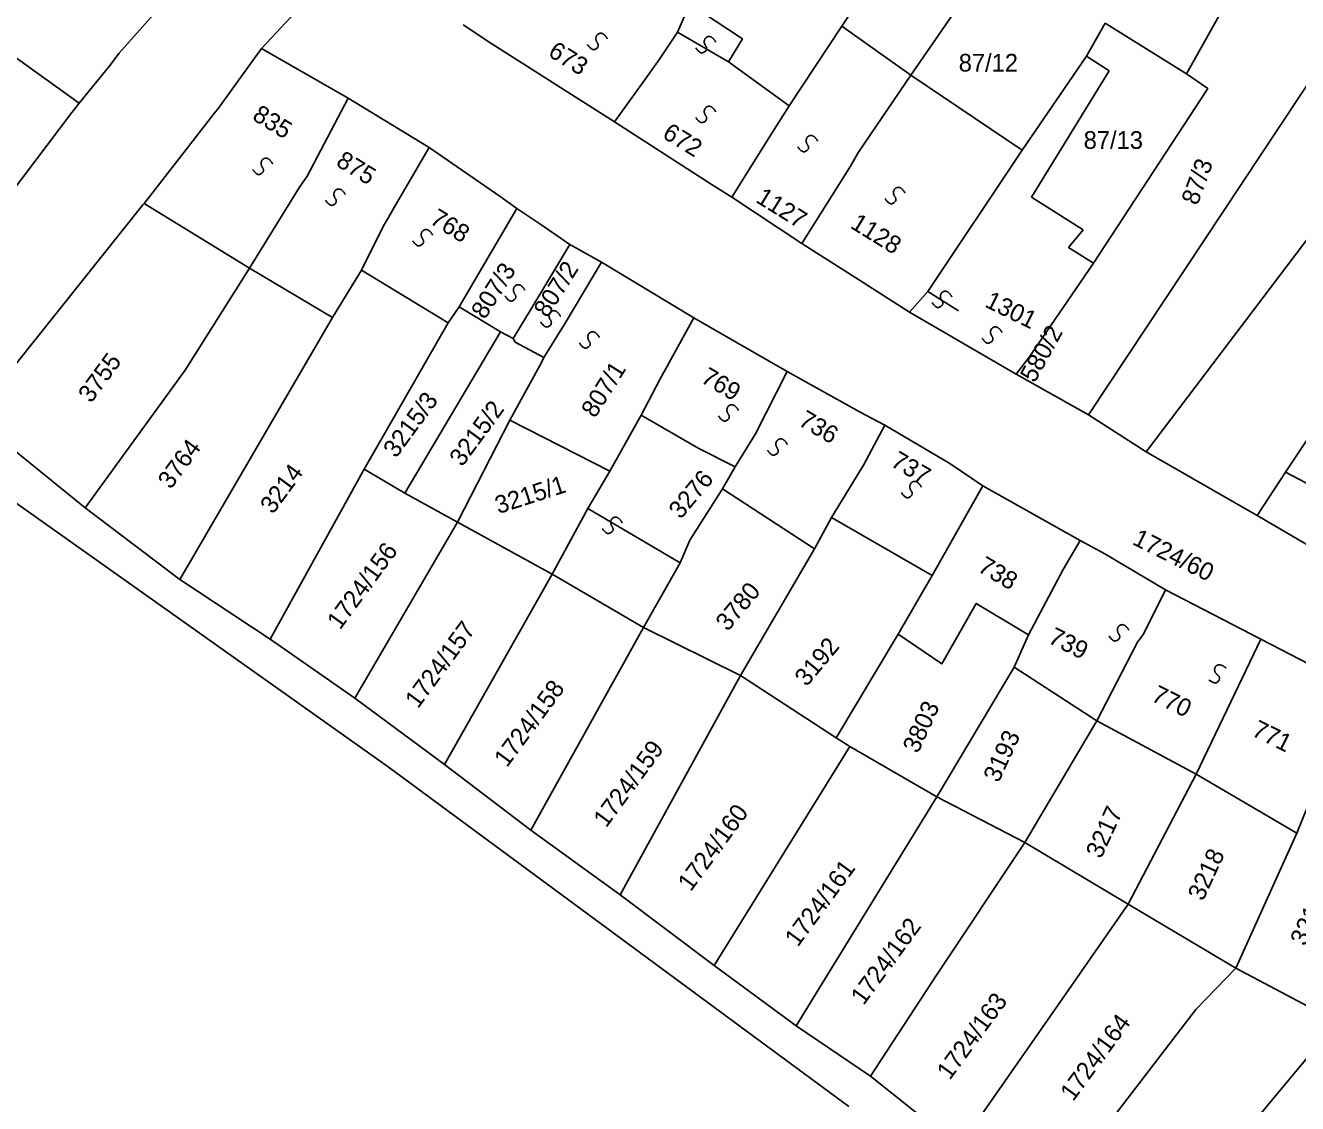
# Model space of a CAD drawing. Extents: x -581999 to -572728, y -1219553 to -1212032.
# Drawn here: x -578351.7 to -578208.2, y -1215913.8 to -1215792.1 of the extents above; entities that cross this region are included whole.
import ezdxf

# ---------------------------------------------------------------- set-up
doc = ezdxf.new("R2010")
doc.units = 0
for name, color, linetype in [('Vrstva 1', 7, 'Continuous'), ('Vrstva 2', 7, 'Continuous'), ('Vrstva 4', 7, 'Continuous'), ('Vrstva 6', 7, 'Continuous')]:
    doc.layers.add(name, color=color, linetype=linetype)

msp = doc.modelspace()

# ---------------------------------------------------------------- linework, layer by layer
at = {"layer": 'Vrstva 1'}
for p, q in [((-578325.082, -1215794.665), (-578314.583, -1215783.383)), ((-578229.44, -1215797.188), (-578231.995, -1215795.54)), ((-578238.201, -1215811.469), (-578229.44, -1215797.188)), ((-578232.36, -1215815.13), (-578238.201, -1215811.469)), ((-578234.003, -1215817.144), (-578232.36, -1215815.13)), ((-578294.134, -1215823.186), (-578290.3, -1215816.778)), ((-578258.024, -1215820.546), (-578264.092, -1215816.665)), ((-578231.196, -1215818.915), (-578234.003, -1215817.144)), ((-578251.957, -1215824.427), (-578258.024, -1215820.546)), ((-578296.689, -1215827.397), (-578294.134, -1215823.186))]:
    msp.add_line(p, q, dxfattribs=at)
for points in [[(-578248.644, -1215775.593), (-578259.602, -1215792.151)], [(-578251.82, -1215797.67), (-578238.821, -1215778.882)], [(-578201.443, -1215790.286), (-578210.075, -1215785.563), (-578215.455, -1215788.156), (-578220.697, -1215797.517)], [(-578278.147, -1215792.82), (-578276.753, -1215789.682)], [(-578276.753, -1215789.682), (-578270.823, -1215793.585), (-578272.401, -1215796.19)], [(-578341.196, -1215795.228), (-578336.766, -1215790.241)], [(-578231.766, -1215836.027), (-578201.443, -1215790.286)], [(-578299.101, -1215794.162), (-578302.325, -1215791.994)], [(-578280.191, -1215795.89), (-578278.147, -1215792.82)], [(-578265.545, -1215801.146), (-578259.602, -1215792.151)], [(-578259.602, -1215792.151), (-578251.82, -1215797.67)], [(-578229.866, -1215791.81), (-578231.995, -1215795.54), (-578239.244, -1215806.132)], [(-578220.697, -1215797.517), (-578229.866, -1215791.81)], [(-578356.273, -1215793.251), (-578345.656, -1215800.846)], [(-578285.27, -1215802.943), (-578299.101, -1215794.162)], [(-578345.656, -1215800.846), (-578342.189, -1215796.566), (-578341.196, -1215795.228)], [(-578325.082, -1215794.665), (-578330.06, -1215801.573), (-578330.304, -1215801.849)], [(-578315.328, -1215800.266), (-578325.082, -1215794.665)], [(-578281.583, -1215797.844), (-578280.191, -1215795.89)], [(-578272.401, -1215796.19), (-578265.545, -1215801.146)], [(-578285.27, -1215802.943), (-578281.583, -1215797.844)], [(-578257.697, -1215806.38), (-578251.82, -1215797.67)], [(-578251.82, -1215797.67), (-578239.244, -1215806.132)], [(-578231.196, -1215818.915), (-578218.29, -1215799.2), (-578220.697, -1215797.517)], [(-578345.656, -1215800.846), (-578346.32, -1215801.667)], [(-578319.926, -1215809.096), (-578315.328, -1215800.266)], [(-578306.151, -1215805.863), (-578315.328, -1215800.266)], [(-578267.402, -1215804.124), (-578265.545, -1215801.146)], [(-578367.768, -1215830.009), (-578346.507, -1215801.898), (-578346.32, -1215801.667)], [(-578330.304, -1215801.849), (-578338.202, -1215811.998), (-578338.344, -1215812.157)], [(-578274.243, -1215810.054), (-578285.27, -1215802.943)], [(-578272.018, -1215811.456), (-578267.402, -1215804.124)], [(-578310.771, -1215813.742), (-578310.219, -1215812.793), (-578306.151, -1215805.863)], [(-578306.151, -1215805.863), (-578298.174, -1215811.369)], [(-578258.621, -1215807.945), (-578257.697, -1215806.38)], [(-578239.244, -1215806.132), (-578249.884, -1215822.088), (-578251.957, -1215824.427)], [(-578264.092, -1215816.665), (-578258.621, -1215807.945)], [(-578320.812, -1215810.318), (-578319.926, -1215809.096)], [(-578272.018, -1215811.456), (-578274.243, -1215810.054)], [(-578326.437, -1215819.457), (-578320.812, -1215810.318)], [(-578298.174, -1215811.369), (-578296.263, -1215812.718)], [(-578264.092, -1215816.665), (-578272.018, -1215811.456)], [(-578338.344, -1215812.157), (-578338.485, -1215812.315), (-578357.631, -1215836.292), (-578345.01, -1215846.507)], [(-578326.437, -1215819.457), (-578338.344, -1215812.157)], [(-578302.784, -1215823.848), (-578296.263, -1215812.718)], [(-578296.263, -1215812.718), (-578293.683, -1215814.455)], [(-578225.23, -1215840.186), (-578204.682, -1215813.018), (-578194.518, -1215819.709)], [(-578311.323, -1215814.691), (-578310.771, -1215813.742)], [(-578293.683, -1215814.455), (-578290.3, -1215816.778), (-578286.706, -1215818.796)], [(-578313.813, -1215819.682), (-578311.323, -1215814.691)], [(-578286.706, -1215818.796), (-578290.824, -1215825.685)], [(-578286.706, -1215818.796), (-578276.291, -1215825.067)], [(-578345.01, -1215846.507), (-578333.714, -1215830.97), (-578326.437, -1215819.457)], [(-578317.068, -1215825.054), (-578326.437, -1215819.457)], [(-578317.068, -1215825.054), (-578313.813, -1215819.682)], [(-578304.02, -1215825.65), (-578313.813, -1215819.682)], [(-578238.437, -1215829.515), (-578231.196, -1215818.915)], [(-578304.02, -1215825.65), (-578302.784, -1215823.848)], [(-578302.784, -1215823.848), (-578298.101, -1215826.646)], [(-578239.915, -1215831.443), (-578251.957, -1215824.427)], [(-578334.303, -1215854.603), (-578317.068, -1215825.054)], [(-578313.5, -1215842.151), (-578304.02, -1215825.65)], [(-578290.824, -1215825.685), (-578293.227, -1215829.541)], [(-578280.123, -1215832.05), (-578276.291, -1215825.067)], [(-578276.291, -1215825.067), (-578273.872, -1215826.482), (-578265.782, -1215831.145)], [(-578308.912, -1215844.852), (-578298.101, -1215826.646)], [(-578298.101, -1215826.646), (-578296.689, -1215827.397), (-578296.476, -1215827.804), (-578293.227, -1215829.541)], [(-578293.227, -1215829.541), (-578293.505, -1215830.098), (-578297.048, -1215836.622)], [(-578239.915, -1215831.443), (-578238.437, -1215829.515)], [(-578265.782, -1215831.145), (-578269.325, -1215838.148)], [(-578257.523, -1215835.708), (-578265.782, -1215831.145)], [(-578231.766, -1215836.027), (-578239.915, -1215831.443)], [(-578201.475, -1215830.426), (-578209.516, -1215842.511)], [(-578282.226, -1215836.06), (-578280.123, -1215832.05)], [(-578285.769, -1215842.392), (-578282.226, -1215836.06)], [(-578282.226, -1215836.06), (-578275.731, -1215839.822), (-578271.623, -1215841.889)], [(-578254.748, -1215837.192), (-578257.523, -1215835.708)], [(-578225.23, -1215840.186), (-578231.766, -1215836.027)], [(-578297.048, -1215836.622), (-578302.986, -1215848.134)], [(-578297.048, -1215836.622), (-578285.769, -1215842.392)], [(-578257.141, -1215841.701), (-578254.748, -1215837.192)], [(-578247.393, -1215841.533), (-578254.748, -1215837.192)], [(-578269.325, -1215838.148), (-578271.623, -1215841.889)], [(-578402.132, -1215909.667), (-578391.501, -1215876.535), (-578369.675, -1215849.108), (-578360.87, -1215840.289), (-578310.778, -1215875.757), (-578269.515, -1215906.185), (-578258.822, -1215914.078)], [(-578212.731, -1215847.387), (-578225.23, -1215840.186)], [(-578260.777, -1215847.615), (-578257.141, -1215841.701)], [(-578243.669, -1215844.039), (-578247.393, -1215841.533)], [(-578324.128, -1215861.338), (-578313.5, -1215842.151)], [(-578313.5, -1215842.151), (-578308.912, -1215844.852)], [(-578288.258, -1215846.612), (-578285.769, -1215842.392)], [(-578271.623, -1215841.889), (-578273.06, -1215844.382)], [(-578209.516, -1215842.511), (-578212.731, -1215847.387)], [(-578273.06, -1215844.382), (-578276.738, -1215850.181), (-578277.847, -1215852.727), (-578281.963, -1215860.016)], [(-578273.06, -1215844.382), (-578262.692, -1215851.164)], [(-578249.411, -1215854.172), (-578243.669, -1215844.039)], [(-578232.687, -1215850.21), (-578243.669, -1215844.039)], [(-578308.912, -1215844.852), (-578302.986, -1215848.134)], [(-578345.01, -1215846.507), (-578334.303, -1215854.603)], [(-578292.28, -1215853.998), (-578288.258, -1215846.612)], [(-578202.918, -1215853.089), (-578212.731, -1215847.387)], [(-578302.986, -1215848.134), (-578314.57, -1215867.99)], [(-578302.986, -1215848.134), (-578292.28, -1215853.998)], [(-578260.777, -1215847.615), (-578262.692, -1215851.164)], [(-578249.411, -1215854.172), (-578260.777, -1215847.615)], [(-578232.687, -1215850.21), (-578234.608, -1215853.48)], [(-578229.92, -1215851.706), (-578232.687, -1215850.21)], [(-578262.692, -1215851.164), (-578271.021, -1215865.452)], [(-578223.075, -1215855.774), (-578229.92, -1215851.706)], [(-578324.128, -1215861.338), (-578334.303, -1215854.603)], [(-578304.439, -1215875.483), (-578292.28, -1215853.998)], [(-578292.28, -1215853.998), (-578281.963, -1215860.016)], [(-578253.241, -1215860.788), (-578249.411, -1215854.172)], [(-578234.608, -1215853.48), (-578238.528, -1215860.855)], [(-578223.075, -1215855.774), (-578225.565, -1215860.76)], [(-578212.307, -1215861.346), (-578223.075, -1215855.774)], [(-578238.528, -1215860.855), (-578244.416, -1215857.303), (-578248.317, -1215864.14), (-578253.241, -1215860.788)], [(-578281.963, -1215860.016), (-578294.694, -1215882.898)], [(-578281.963, -1215860.016), (-578271.021, -1215865.452)], [(-578314.57, -1215867.99), (-578324.128, -1215861.338)], [(-578260.229, -1215872.486), (-578253.241, -1215860.788)], [(-578238.528, -1215860.855), (-578240.157, -1215864.5)], [(-578226.226, -1215861.692), (-578230.831, -1215870.54)], [(-578225.565, -1215860.76), (-578226.226, -1215861.692)], [(-578214.797, -1215866.524), (-578212.307, -1215861.346)], [(-578212.307, -1215861.346), (-578201.33, -1215867.035)], [(-578240.157, -1215864.5), (-578248.865, -1215879.136)], [(-578240.157, -1215864.5), (-578230.831, -1215870.54)], [(-578284.616, -1215890.193), (-578271.021, -1215865.452)], [(-578271.021, -1215865.452), (-578260.229, -1215872.486)], [(-578219.585, -1215876.592), (-578214.797, -1215866.524)], [(-578314.57, -1215867.99), (-578304.439, -1215875.483)], [(-578238.939, -1215884.305), (-578230.831, -1215870.54)], [(-578230.831, -1215870.54), (-578219.585, -1215876.592)], [(-578258.701, -1215873.45), (-578260.229, -1215872.486)], [(-578274.015, -1215898.185), (-578258.701, -1215873.45)], [(-578258.701, -1215873.45), (-578248.865, -1215879.136)], [(-578294.694, -1215882.898), (-578304.439, -1215875.483)], [(-578227.293, -1215891.241), (-578219.585, -1215876.592)], [(-578219.585, -1215876.592), (-578208.228, -1215883.24)], [(-578248.865, -1215879.136), (-578264.757, -1215904.982)], [(-578238.939, -1215884.305), (-578248.865, -1215879.136)], [(-578206.643, -1215879.549), (-578206.886, -1215879.884), (-578208.228, -1215883.24)], [(-578294.694, -1215882.898), (-578284.616, -1215890.193)], [(-578208.228, -1215883.24), (-578215.124, -1215898.484)], [(-578256.355, -1215910.663), (-578248.891, -1215899.257), (-578238.939, -1215884.305)], [(-578227.293, -1215891.241), (-578238.939, -1215884.305)], [(-578284.616, -1215890.193), (-578274.015, -1215898.185)], [(-578246.333, -1215918.648), (-578235.235, -1215902.742), (-578227.293, -1215891.241)], [(-578215.124, -1215898.484), (-578227.293, -1215891.241)], [(-578264.757, -1215904.982), (-578274.015, -1215898.185)], [(-578219.625, -1215903.123), (-578215.124, -1215898.484)], [(-578215.124, -1215898.484), (-578203.706, -1215904.526)], [(-578236.728, -1215925.423), (-578219.625, -1215903.123)], [(-578264.757, -1215904.982), (-578256.355, -1215910.663)], [(-578227.09, -1215932.638), (-578203.706, -1215904.526)], [(-578256.355, -1215910.663), (-578246.333, -1215918.648)]]:
    msp.add_lwpolyline(points, dxfattribs=at)
at = {"layer": 'Vrstva 4'}
msp.add_line((-578246.416, -1215824.285), (-578249.884, -1215822.088), dxfattribs=at)
for points in [[(-578278.147, -1215792.82), (-578272.401, -1215796.19)], [(-578200.268, -1215847.328), (-578209.516, -1215842.511)], [(-578288.258, -1215846.612), (-578277.847, -1215852.727)]]:
    msp.add_lwpolyline(points, dxfattribs=at)
at = {"layer": 'Vrstva 6'}
for points in [[(-578288.306, -1215794.221), (-578287.826, -1215794.928), (-578287.132, -1215794.617), (-578287.055, -1215794.217), (-578287.291, -1215793.872), (-578287.376, -1215793.54), (-578287.294, -1215793.25), (-578287.15, -1215793.07), (-578286.914, -1215792.942), (-578286.549, -1215792.978), (-578286.122, -1215793.417), (-578286.067, -1215793.59)], [(-578276.076, -1215794.588), (-578275.596, -1215795.295), (-578274.902, -1215794.984), (-578274.825, -1215794.584), (-578275.061, -1215794.239), (-578275.146, -1215793.907), (-578275.064, -1215793.617), (-578274.92, -1215793.437), (-578274.684, -1215793.309), (-578274.319, -1215793.345), (-578273.892, -1215793.784), (-578273.837, -1215793.957)], [(-578276.076, -1215802.46), (-578275.596, -1215803.167), (-578274.902, -1215802.856), (-578274.825, -1215802.456), (-578275.061, -1215802.111), (-578275.146, -1215801.779), (-578275.064, -1215801.489), (-578274.92, -1215801.309), (-578274.684, -1215801.181), (-578274.319, -1215801.217), (-578273.892, -1215801.656), (-578273.837, -1215801.829)], [(-578264.576, -1215805.756), (-578264.096, -1215806.463), (-578263.402, -1215806.152), (-578263.325, -1215805.752), (-578263.561, -1215805.407), (-578263.646, -1215805.075), (-578263.564, -1215804.785), (-578263.42, -1215804.605), (-578263.184, -1215804.477), (-578262.819, -1215804.513), (-578262.392, -1215804.952), (-578262.337, -1215805.125)], [(-578326.092, -1215808.319), (-578325.612, -1215809.026), (-578324.918, -1215808.715), (-578324.841, -1215808.315), (-578325.077, -1215807.97), (-578325.162, -1215807.638), (-578325.08, -1215807.348), (-578324.936, -1215807.168), (-578324.7, -1215807.04), (-578324.335, -1215807.076), (-578323.908, -1215807.515), (-578323.853, -1215807.688)], [(-578317.877, -1215811.798), (-578317.397, -1215812.505), (-578316.703, -1215812.194), (-578316.626, -1215811.794), (-578316.862, -1215811.449), (-578316.947, -1215811.117), (-578316.865, -1215810.827), (-578316.721, -1215810.647), (-578316.485, -1215810.519), (-578316.12, -1215810.555), (-578315.693, -1215810.994), (-578315.638, -1215811.167)], [(-578254.719, -1215811.615), (-578254.239, -1215812.322), (-578253.545, -1215812.011), (-578253.468, -1215811.611), (-578253.704, -1215811.266), (-578253.789, -1215810.934), (-578253.707, -1215810.644), (-578253.563, -1215810.464), (-578253.327, -1215810.336), (-578252.962, -1215810.372), (-578252.535, -1215810.811), (-578252.48, -1215810.984)], [(-578308.02, -1215816.375), (-578307.54, -1215817.082), (-578306.846, -1215816.771), (-578306.769, -1215816.371), (-578307.005, -1215816.026), (-578307.09, -1215815.694), (-578307.008, -1215815.404), (-578306.864, -1215815.224), (-578306.628, -1215815.096), (-578306.263, -1215815.132), (-578305.836, -1215815.571), (-578305.781, -1215815.744)], [(-578297.615, -1215822.6), (-578297.135, -1215823.307), (-578296.441, -1215822.996), (-578296.364, -1215822.596), (-578296.6, -1215822.251), (-578296.685, -1215821.919), (-578296.603, -1215821.629), (-578296.459, -1215821.449), (-578296.223, -1215821.321), (-578295.858, -1215821.357), (-578295.431, -1215821.796), (-578295.376, -1215821.969)], [(-578249.425, -1215823.333), (-578248.945, -1215824.04), (-578248.251, -1215823.729), (-578248.174, -1215823.329), (-578248.41, -1215822.984), (-578248.495, -1215822.652), (-578248.413, -1215822.362), (-578248.269, -1215822.182), (-578248.033, -1215822.054), (-578247.668, -1215822.09), (-578247.241, -1215822.529), (-578247.186, -1215822.702)], [(-578293.6, -1215825.529), (-578293.12, -1215826.236), (-578292.426, -1215825.925), (-578292.349, -1215825.525), (-578292.585, -1215825.18), (-578292.67, -1215824.848), (-578292.588, -1215824.558), (-578292.444, -1215824.378), (-578292.208, -1215824.25), (-578291.843, -1215824.286), (-578291.416, -1215824.725), (-578291.361, -1215824.898)], [(-578289.219, -1215827.909), (-578288.739, -1215828.616), (-578288.045, -1215828.305), (-578287.968, -1215827.905), (-578288.204, -1215827.56), (-578288.289, -1215827.228), (-578288.207, -1215826.938), (-578288.063, -1215826.758), (-578287.827, -1215826.63), (-578287.462, -1215826.666), (-578287.035, -1215827.105), (-578286.98, -1215827.278)], [(-578243.766, -1215827.36), (-578243.286, -1215828.067), (-578242.592, -1215827.756), (-578242.515, -1215827.356), (-578242.751, -1215827.011), (-578242.836, -1215826.679), (-578242.754, -1215826.389), (-578242.61, -1215826.209), (-578242.374, -1215826.081), (-578242.009, -1215826.117), (-578241.582, -1215826.556), (-578241.527, -1215826.729)], [(-578273.52, -1215836.148), (-578273.04, -1215836.855), (-578272.346, -1215836.544), (-578272.269, -1215836.144), (-578272.505, -1215835.799), (-578272.59, -1215835.467), (-578272.508, -1215835.177), (-578272.364, -1215834.997), (-578272.128, -1215834.869), (-578271.763, -1215834.905), (-578271.336, -1215835.344), (-578271.281, -1215835.517)], [(-578267.992, -1215839.998), (-578267.512, -1215840.705), (-578266.818, -1215840.394), (-578266.741, -1215839.994), (-578266.977, -1215839.649), (-578267.062, -1215839.317), (-578266.98, -1215839.027), (-578266.836, -1215838.847), (-578266.6, -1215838.719), (-578266.235, -1215838.755), (-578265.808, -1215839.194), (-578265.753, -1215839.367)], [(-578252.878, -1215844.799), (-578252.398, -1215845.506), (-578251.704, -1215845.195), (-578251.627, -1215844.795), (-578251.863, -1215844.45), (-578251.948, -1215844.118), (-578251.866, -1215843.828), (-578251.722, -1215843.648), (-578251.486, -1215843.52), (-578251.121, -1215843.556), (-578250.694, -1215843.995), (-578250.639, -1215844.168)], [(-578286.633, -1215848.841), (-578286.153, -1215849.548), (-578285.459, -1215849.237), (-578285.382, -1215848.837), (-578285.618, -1215848.492), (-578285.703, -1215848.16), (-578285.621, -1215847.87), (-578285.477, -1215847.69), (-578285.241, -1215847.562), (-578284.876, -1215847.598), (-578284.449, -1215848.037), (-578284.394, -1215848.21)], [(-578229.45, -1215860.969), (-578228.97, -1215861.676), (-578228.276, -1215861.365), (-578228.199, -1215860.965), (-578228.435, -1215860.62), (-578228.52, -1215860.288), (-578228.438, -1215859.998), (-578228.294, -1215859.818), (-578228.058, -1215859.69), (-578227.693, -1215859.726), (-578227.266, -1215860.165), (-578227.211, -1215860.338)], [(-578218.168, -1215865.938), (-578217.485, -1215866.451), (-578216.929, -1215865.931), (-578216.987, -1215865.528), (-578217.323, -1215865.278), (-578217.51, -1215864.992), (-578217.527, -1215864.691), (-578217.45, -1215864.474), (-578217.268, -1215864.277), (-578216.911, -1215864.192), (-578216.365, -1215864.468), (-578216.256, -1215864.614)]]:
    msp.add_open_spline(points, degree=2, dxfattribs=at)

# ---------------------------------------------------------------- texts
at = {"layer": 'Vrstva 2'}
for s, rotation, p in [('673', 328.31145, (-578292.861, -1215795.446)), ('835', 328.31145, (-578326.258, -1215802.622)), ('672', 328.31145, (-578279.966, -1215804.671)), ('875', 328.31145, (-578316.808, -1215807.815)), ('87/3', 69.85149, (-578219.459, -1215812.472)), ('1127', 328.31145, (-578269.42, -1215811.951)), ('768', 328.31145, (-578306.213, -1215814.337)), ('1128', 328.31145, (-578258.751, -1215814.858)), ('807/2', 57.66681, (-578292.812, -1215825.17)), ('807/3', 57.66681, (-578299.882, -1215825.343)), ('1301', 333.83334, (-578243.578, -1215823.767)), ('580/2', 60.91474, (-578237.84, -1215832.505)), ('3755', 53.74004, (-578344.327, -1215834.791)), ('807/1', 57.66681, (-578287.455, -1215836.482)), ('769', 329.62345, (-578275.634, -1215832.274)), ('3215/3', 53.74004, (-578309.905, -1215840.99)), ('3215/2', 53.74004, (-578302.433, -1215841.969)), ('736', 329.62345, (-578264.618, -1215837.116)), ('3764', 53.74004, (-578335.337, -1215844.519)), ('737', 329.62345, (-578254.202, -1215841.729)), ('3214', 53.74004, (-578323.794, -1215847.321)), ('3215/1', 17.91564, (-578298.358, -1215847.231)), ('3276', 50.15892, (-578277.772, -1215847.892)), ('1724/156', 53.74004, (-578316.226, -1215860.378)), ('1724/60', 333.68301, (-578226.911, -1215850.592)), ('738', 329.62345, (-578244.38, -1215853.609)), ('3780', 50.15892, (-578272.471, -1215860.549)), ('1724/157', 53.74004, (-578307.434, -1215869.265)), ('739', 333.68301, (-578236.438, -1215861.707)), ('3192', 50.15892, (-578263.561, -1215866.784)), ('1724/158', 53.74004, (-578297.386, -1215875.901)), ('770', 333.68301, (-578224.779, -1215868.246)), ('3803', 65.27093, (-578251.003, -1215874.332)), ('771', 333.68301, (-578213.452, -1215872.173)), ('3193', 65.27093, (-578241.898, -1215877.633)), ('1724/159', 53.74004, (-578286.19, -1215882.713)), ('1724/160', 53.74004, (-578276.642, -1215889.913)), ('3217', 65.27093, (-578230.335, -1215886.218)), ('3218', 65.27093, (-578218.826, -1215890.994)), ('1724/161', 53.74004, (-578264.567, -1215896.174)), ('3219', 65.27093, (-578207.278, -1215896.081)), ('1724/162', 53.74004, (-578257.138, -1215902.747)), ('1724/163', 53.74004, (-578247.414, -1215911.195)), ('1724/164', 53.74004, (-578233.489, -1215913.596))]:
    msp.add_text(s, height=2, rotation=rotation, dxfattribs=at).set_placement(p)
for s, p in [('87/12', (-578246.402, -1215797.281)), ('87/13', (-578232.301, -1215806.004))]:
    msp.add_text(s, height=2, dxfattribs=at).set_placement(p)

doc.saveas('drawing.dxf')
